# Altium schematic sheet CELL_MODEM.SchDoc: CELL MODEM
size A3; Author: Arturo Guadalupi; CompanyName: Arduino srl; DocumentNumber: ABX00043; SheetNumber: 5; SheetTotal: 14; RevAuthor: S. Navaretti
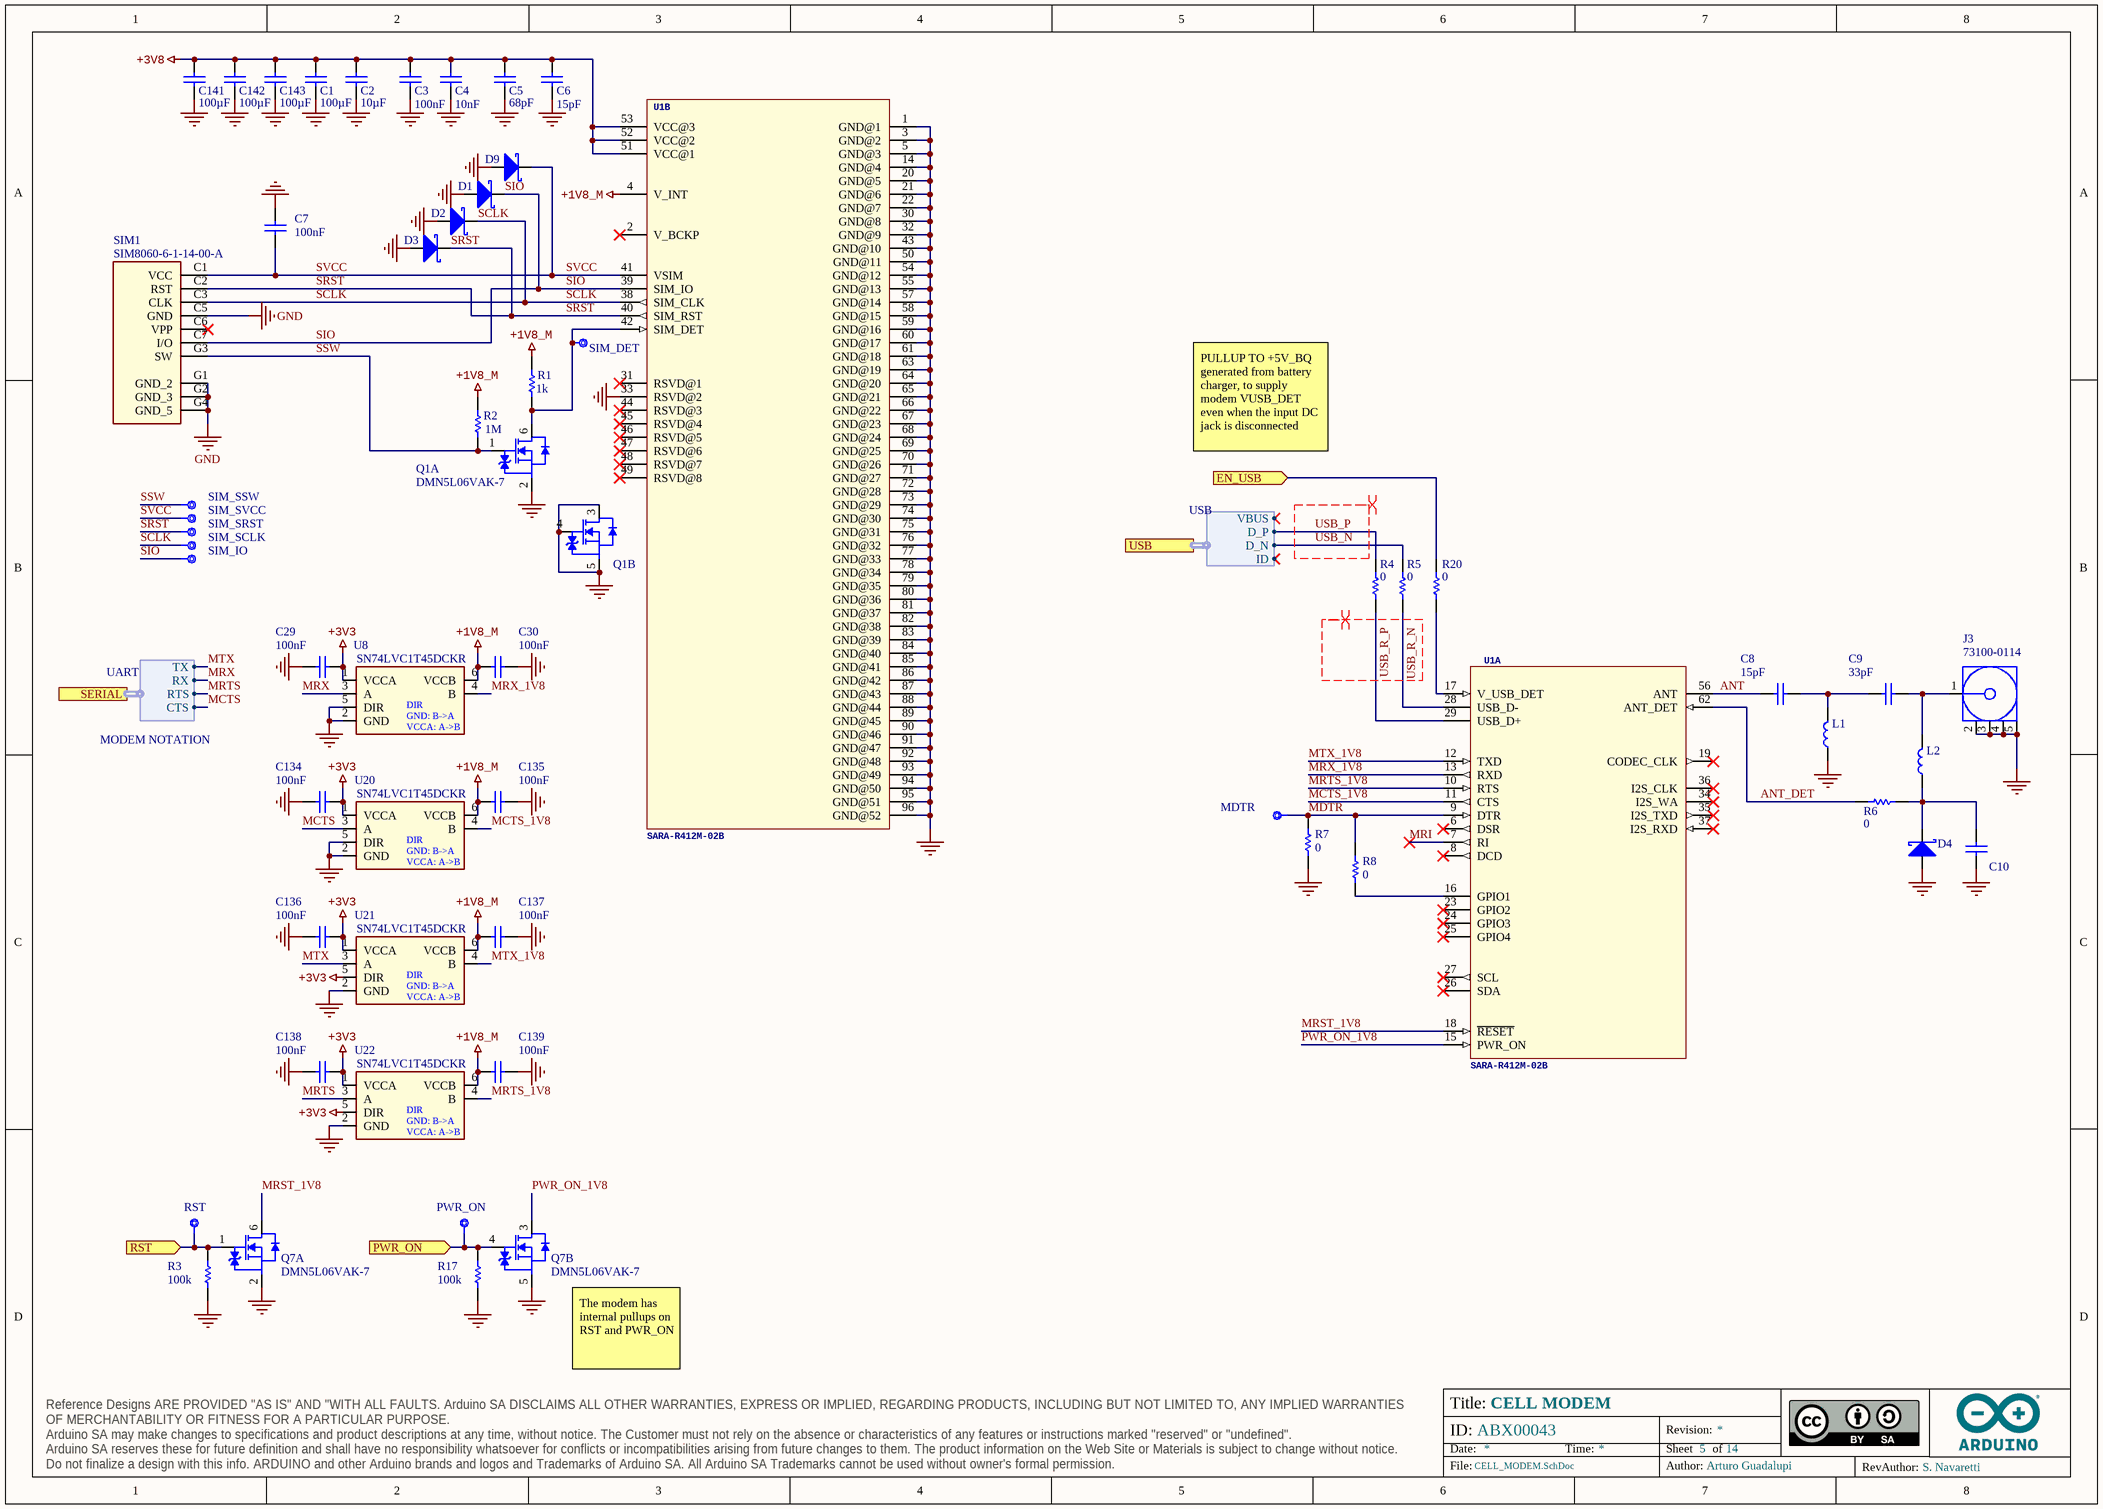
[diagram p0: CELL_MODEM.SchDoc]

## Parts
C1  value 100µF  [CAP-1206]  (hidden comment: CL31A107MPHNNNE)
C2  value 10µF  [CAP-0603]  (hidden comment: GRM188R61E106MA73J)
C3  value 100nF  [CAP-0402]  (hidden comment: C0402C104K4RACTU)
C4  value 10nF  [CAP-0402]  (hidden comment: C0402C103K5RACTU)
C5  value 68pF  [CAP-0402]  (hidden comment: 04025A680JAT2A)
C6  value 15pF  [CAP-0402]  (hidden comment: C0402C150J5GACTU)
C7  value 100nF  [CAP-0402]  (hidden comment: C0402C104K4RACTU)
C8  value 15pF  [CAP-0402]  (hidden comment: C0402C150J5GACTU)
C9  value 33pF  [CAP-0402]  (hidden comment: GRM1555C1H330JA01D)
C10  C0402C104K4RACTU  [CAP-0402]  (value not drawn)
C29  value 100nF  [CAP-0402]  (hidden comment: C0402C104K4RACTU)
C30  value 100nF  [CAP-0402]  (hidden comment: C0402C104K4RACTU)
C134  value 100nF  [CAP-0402]  (hidden comment: C0402C104K4RACTU)
C135  value 100nF  [CAP-0402]  (hidden comment: C0402C104K4RACTU)
C136  value 100nF  [CAP-0402]  (hidden comment: C0402C104K4RACTU)
C137  value 100nF  [CAP-0402]  (hidden comment: C0402C104K4RACTU)
C138  value 100nF  [CAP-0402]  (hidden comment: C0402C104K4RACTU)
C139  value 100nF  [CAP-0402]  (hidden comment: C0402C104K4RACTU)
C141  value 100µF  [CAP-1206]  (hidden comment: CL31A107MPHNNNE)
C142  value 100µF  [CAP-1206]  (hidden comment: CL31A107MPHNNNE)
C143  value 100µF  [CAP-1206]  (hidden comment: CL31A107MPHNNNE)
D1  PESD0402-140CT-ND  [0402]  (value not drawn)
D2  PESD0402-140CT-ND  [0402]  (value not drawn)
D3  PESD0402-140CT-ND  [0402]  (value not drawn)
D4  PESD0402-140CT-ND  [0402]  (value not drawn)
D9  PESD0402-140CT-ND  [0402]  (value not drawn)
J3  73100-0114  [MOLX-731000114_V]
L1  LQG15HN39NJ02D  [0402]  (value not drawn)
L2  LQG15HS68NJ02D  [0402]  (value not drawn)
MDTR  CMP-018-0005-A.3  [TP-1.00MM]  (value not drawn)  (no BOM)
PWR_ON  CMP-018-0005-A.3  [TP-1.00MM]  (value not drawn)  (no BOM)
Q1  DMN5L06VAK-7  [SOTFL50P158X60-6N]  (parts A,B of 2)
Q7  DMN5L06VAK-7  [SOTFL50P158X60-6N]  (parts A,B of 2)
R1  value 1k  [RES-0402]  (hidden comment: CRCW04021K00FKEDC)
R2  value 1M  [RES-0402]  (hidden comment: CRCW04021M00FKED)
R3  value 100k  [RES-0402]  (hidden comment: CRCW0402100KFKEDC)
R4  value 0  [RES-0402]  (hidden comment: CRCW04020000Z0EDC)
R5  value 0  [RES-0402]  (hidden comment: CRCW04020000Z0EDC)
R6  value 0  [RES-0402]  (hidden comment: CRCW04020000Z0EDC)
R7  value 0  [RES-0402]  (hidden comment: CRCW04020000Z0EDC)
R8  value 0  [RES-0402]  (hidden comment: CRCW04020000Z0EDC)
R17  value 100k  [RES-0402]  (hidden comment: CRCW0402100KFKEDC)
R20  value 0  [RES-0402]  (hidden comment: CRCW04020000Z0EDC)
RST  CMP-018-0005-A.3  [TP-1.00MM]  (value not drawn)  (no BOM)
SIM1  SIM8060-6-1-14-00-A  [SIM8060-6-0-14-00-A-Footprint-1]
SIM_DET  CMP-018-0005-A.3  [TP-1.00MM]  (value not drawn)  (no BOM)
SIM_IO  CMP-018-0005-A.3  [TP-1.00MM]  (value not drawn)  (no BOM)
SIM_SCLK  CMP-018-0005-A.3  [TP-1.00MM]  (value not drawn)  (no BOM)
SIM_SRST  CMP-018-0005-A.3  [TP-1.00MM]  (value not drawn)  (no BOM)
SIM_SSW  CMP-018-0005-A.3  [TP-1.00MM]  (value not drawn)  (no BOM)
SIM_SVCC  CMP-018-0005-A.3  [TP-1.00MM]  (value not drawn)  (no BOM)
U1  SARA-R412M-02B  [SARA-96]  (parts A,B of 2)
U8  SN74LVC1T45DCKR  [sc70-6]
U20  SN74LVC1T45DCKR  [sc70-6]
U21  SN74LVC1T45DCKR  [sc70-6]
U22  SN74LVC1T45DCKR  [sc70-6]

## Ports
EN_USB (in), PWR_ON (in), RST (in), SERIAL (harness UART), USB (harness USB)

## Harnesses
USB: VBUS, D_N, D_P, ID
UART: RX, TX, RTS, CTS

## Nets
+1V8_M: C30.2 C135.2 C137.2 C139.2 R1.2 R2.2 U1.4(V_INT) U8.6(VCCB) U20.6(VCCB) U21.6(VCCB) U22.6(VCCB)
+3V3: C29.2 C134.2 C136.2 C138.2 U8.1(VCCA) U20.1(VCCA) U21.1(VCCA) U21.5(DIR) U22.1(VCCA) U22.5(DIR)
+3V8: C1.2 C2.2 C3.2 C4.2 C5.2 C6.2 C141.2 C142.2 C143.2 U1.51(VCC@1) U1.52(VCC@2) U1.53(VCC@3)
GND: C1.1 C2.1 C3.1 C4.1 C5.1 C6.1 C7.2 C10.1 C29.1 C30.1 C134.1 C135.1 C136.1 C137.1 C138.1 C139.1 C141.1 C142.1 C143.1 D1.A D2.A D3.A D4.A D9.A J3.2 J3.3 J3.4 J3.5 L1.1 Q1.2(SOURCEA) Q1.3(DRAINB) Q1.4(GATEB) Q1.5(SOURCEB) Q7.2(SOURCEA) Q7.5(SOURCEB) R3.1 R7.1 R17.1 SIM1.C5(GND) SIM1.G1(GND_2) SIM1.G2(GND_3) SIM1.G4(GND_5) U1.1(GND@1) U1.3(GND@2) U1.5(GND@3) U1.14(GND@4) U1.20(GND@5) U1.21(GND@6) U1.22(GND@7) U1.30(GND@8) U1.32(GND@9) U1.33(RSVD@2) U1.43(GND@10) U1.50(GND@11) U1.54(GND@12) U1.55(GND@13) U1.57(GND@14) U1.58(GND@15) U1.59(GND@16) U1.60(GND@17) U1.61(GND@18) U1.63(GND@19) U1.64(GND@20) U1.65(GND@21) U1.66(GND@22) U1.67(GND@23) U1.68(GND@24) U1.69(GND@25) U1.70(GND@26) U1.71(GND@27) U1.72(GND@28) U1.73(GND@29) U1.74(GND@30) U1.75(GND@31) U1.76(GND@32) U1.77(GND@33) U1.78(GND@34) U1.79(GND@35) U1.80(GND@36) U1.81(GND@37) U1.82(GND@38) U1.83(GND@39) U1.84(GND@40) U1.85(GND@41) U1.86(GND@42) U1.87(GND@43) U1.88(GND@44) U1.89(GND@45) U1.90(GND@46) U1.91(GND@47) U1.92(GND@48) U1.93(GND@49) U1.94(GND@50) U1.95(GND@51) U1.96(GND@52) U8.2(GND) U8.5(DIR) U20.2(GND) U20.5(DIR) U21.2(GND) U22.2(GND)
ANT: C8.1 U1.56(ANT)
ANT_DET: R6.1 U1.62(ANT_DET)
EN_USB: R20.2 ; port EN_USB
MCTS: U20.3(A) ; port SERIAL.CTS
MCTS_1V8: U1.11(CTS) U20.4(B)
MDTR: MDTR.X R7.2 R8.2 U1.9(DTR)
MRI: U1.7(RI)
MRST_1V8: Q7.6(DRAINA) U1.18(~{RESET})
MRTS: U22.3(A) ; port SERIAL.RTS
MRTS_1V8: U1.10(RTS) U22.4(B)
MRX: U8.3(A) ; port SERIAL.RX
MRX_1V8: U1.13(RXD) U8.4(B)
MTX: U21.3(A) ; port SERIAL.TX
MTX_1V8: U1.12(TXD) U21.4(B)
PWR_ON: PWR_ON.X Q7.4(GATEB) R17.2 ; port PWR_ON
PWR_ON_1V8: Q7.3(DRAINB) U1.15(PWR_ON)
RST: Q7.1(GATEA) R3.2 RST.X ; port RST
SCLK: D2.C SIM1.C3(CLK) SIM_SCLK.X U1.38(SIM_CLK)
SIO: D1.C SIM1.C7(I/O) SIM_IO.X U1.39(SIM_IO)
SRST: D3.C SIM1.C2(RST) SIM_SRST.X U1.40(SIM_RST)
SSW: Q1.1(GATEA) R2.1 SIM1.G3(SW) SIM_SSW.X
SVCC: C7.1 D9.C SIM1.C1(VCC) SIM_SVCC.X U1.41(VSIM)
USB_N: R5.2 ; port USB.D_N
USB_P: R4.2 ; port USB.D_P
USB_R_N: R5.1 U1.28(USB_D-)
USB_R_P: R4.1 U1.29(USB_D+)
NetC8_2: C8.2 C9.1 L1.2
NetC9_2: C9.2 J3.1 L2.2
NetC10_2: C10.2 D4.C L2.1 R6.2
NetQ1_6: Q1.6(DRAINA) R1.1 SIM_DET.X U1.42(SIM_DET)
NetR8_1: R8.1 U1.16(GPIO1)
NetR20_1: R20.1 U1.17(V_USB_DET)

Not connected (* = marked no-connect by the designer): SIM1 C6(VPP)*; U1 2(V_BCKP)* 6(DSR)* 8(DCD)* 19(CODEC_CLK)* 23(GPIO2)* 24(GPIO3)* 25(GPIO4)* 26(SDA)* 27(SCL)* 31(RSVD@1)* 34(I2S_WA)* 35(I2S_TXD)* 36(I2S_CLK)* 37(I2S_RXD)* 44(RSVD@3)* 45(RSVD@4)* 46(RSVD@5)* 47(RSVD@6)* 48(RSVD@7)* 49(RSVD@8)*

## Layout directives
differential pair; differential pair class USB: USB_N, USB_P, USB_R_N, USB_R_P

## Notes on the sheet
- PULLUP TO +5V_BQ generated from battery charger, to supply modem VUSB_DET even when the input DC jack is disconnected
- MODEM NOTATION
- (near Q7) The modem has internal pullups on RST and PWR_ON

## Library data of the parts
C1 C141-C143 = C0062-A.9: CAP CHIP 1206 100UF 10V X5R 20%; Manufacturer: Samsung; Code Arduino: A5503
C2 = C0047-A.12: CAP CHIP 0603 10uF 25V X5R 20%; Manufacturer: Murata; Part Number: C1608X5R1A226MT000N; Code Arduino: 2213
C3 C7 C10 C29 C30 C134-C139 = C0012-A.9: CAP CHIP 0402 100nF 16V X7R 10%; Manufacturer: KEMET; Code Arduino: 0132
C4 = C0009-A.9: CAP CHIP 0402 10nF 50V X7R 10%; Manufacturer: KEMET; Code Arduino: 0165
C5 = C0032-A.7: CAP CHIP 0402 68pF C0G 50V 5%; Manufacturer: AVX; Code Arduino: A5496
C6 C8 = C0025-A.9: CAP CHIP 0402 15PF 50V C0G 5%; Manufacturer: Murata; Code Arduino: A5498
C9 = C0034-A.9: CAP CHIP 0402 33PF 50V C0G 5%; Manufacturer: Murata; Code Arduino: A5494
D1-D4 D9 = D0027-A.3: DIODE TVS SMD 0402 14V 40V; Manufacturer: Littelfuse Inc; Code Arduino: 2280; Device Type: ESD protection
J3 = J0084-A.2: CONN PCB JACK RECEPTACLE SMA RA 50 OHM; Manufacturer: Molex; Impedance: 50R; Dielectric Material: PTFE; Body Plating: Gold; Connector Type: SMA,Socket; Frequency: 12Hz; Max Frequency: 18GHz; Code Arduino: J0084; Body Material: Brass; Voltage Rating: 500V
L1 = I0023-A.4: IND CHIP 0402 39NH; Manufacturer: Murata; Code Arduino: A5497; Current: 250mA
L2 = I0020-A.4: IND CHIP 0402 68NH 250MA 5%; Manufacturer: Murata; Code Arduino: A5499
MDTR PWR_ON RST SIM_DET SIM_IO SIM_SCLK SIM_SRST SIM_SSW SIM_SVCC = UT0013-A.2: Test point 1.00mm
Q1 Q7 = T0023-A.5: MOSFET 2N-CH 50V 0.28A SOT-563; Manufacturer: Diodes Incorporated; Number of Elements: 2; Code Arduino: T0023; Element Configuration: Dual; FET Type: 2 N-Channel; Max Power Dissipation: 250mW; Gate to Source Voltage (Vgs): 20V; Continuous Drain Current (ID): 280mA; Rds On Max: 2R; Input Capacitance: 50pF
R1 = R0007-A.15: RES CHIP 0402 1k 1% 1/16W; Manufacturer: Vishay; Code Arduino: 0140; Power: 63mW
R2 = R0058-A.5: RES CHIP 0402 1M 1% 1/16W; Manufacturer: Vishay; Code Arduino: 0139; Power: 63mW
R3 R17 = R0001-A.5: RES CHIP 0402 100K 1% 1/16W; Manufacturer: Vishay; Code Arduino: 0134; Power: 63mW
R4 R5 R20 = R0000-A.5: RES CHIP 0402 0R 1/16W; Manufacturer: Vishay; Tolerance: J; Code Arduino: 0039; Power: 63mW
R6-R8 = R0000-A.5: RES CHIP 0402 0R 1/16W; Manufacturer: Vishay; Code Arduino: 0039; Tolerance: J; Power: 63mW
SIM1 = J0300-A.1: CONN SIM NANO HINGED WITH SWITCH, 6P, 1.40MM PROF; Manufacturer: GCT; Code Arduino: J0300
U1 = M0006-A.4: MODULE RF TXRX CELL 4G LTE CATM1/NB-IOT; Manufacturer: UBlox
U8 U20-U22 = U0019-A.7: IC TRANSLATOR BIDIR 1CH; Manufacturer: Texas Instruments; Device Type: BIDIR LEVEL SHIFTER; Code Arduino: A5331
